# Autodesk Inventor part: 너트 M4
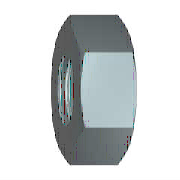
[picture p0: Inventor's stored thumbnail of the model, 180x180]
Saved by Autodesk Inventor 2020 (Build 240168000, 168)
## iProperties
IsCustomPart: 0
Created: 2012-02
Part Number: 너트 M4
Material: 스테인리스강
Description: 6각 너트, 스타일 1 - 제품 등급 A 및 B
Document SubType Name: Modeling
Standard: ISO 4032
Designer: mduedu
Standard Revision: Third edition 1999-08-15
Standards Organization: ISO
Language: ko-KR
Size Designation: M4
Categories: <MemberInstance><Categories><Category DisplayName="조임쇠" InternalName="e4da775c-781d-43d5-af7c-5136215cf5a6" Mnemonic="FSTN"><Category DisplayName="너트" InternalN
Density: 8.08 g/cm^3
Mass: 0.820715 g
Surface Area: 1.59496 cm^2
Volume: 0.101574 cm^3
Appearance: 반광택
Author: mduedu
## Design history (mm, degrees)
sketch "스케치1"
  geometry: L1 (-4.041, 0)-(-2.021, 3.5); L2 (-2.021, 3.5)-(2.021, 3.5); L3 (2.021, 3.5)-(4.041, 0); L4 (4.041, 0)-(2.021, -3.5); L5 (2.021, -3.5)-(-2.021, -3.5); L6 (-2.021, -3.5)-(-4.041, 0); 2 further points
  constraints: 12 end point, 1 coincident, 1 horizontal, 11 other
  dimensions: "d0" = 8.0829 distance of L3.end L1.start (= 1.1547 x SW)
extrude "본체" new body sketch "스케치1" distance "d1" = 3.2 (= KOH); taper "d2" = 0 deg
sketch "스케치2"
  geometry: L1 (0, 2.021)-(0, 4.041) reference; L2 (0, 4.041)-(3.2, 4.041) reference; L3 (3.2, 2.021)-(3.2, 4.041) reference; L4 (-0.64, 0)-(3.84, 0) reference; L5 (0.63, 4.041)-(0, 2.95); L6 (2.57, 4.041)-(3.2, 2.95)
  constraints: 4 end point, 4 point on line
  dimensions: "d3" = 30 deg angle of L1 L5 (= ANG1); "d4" = 30 deg angle of L3 L6 (= ANG2); "d5" = 5.9 diameter of L5.end L4 (= SW0); "d6" = 5.9 diameter of L6.end L4 (= SW01)
revolve "모따기1" sketch "스케치2" stored, may be unused: angle "d7" = 90 deg
sketch "스케치3"
  geometry: 4 further points
  constraints: 1 coincident, 1 other
hole "스레드" sketch "스케치3" at (0, 0) diameter "d25" = 3.242; stored, may be unused: countersink angle "d29" = 82 deg, drill point angle "d31" = 118 deg; dims "d26" = 6, "d27" = 4, "d28" = 2, "d30" = 8
workaxis "Work Axis1"
workplane "Work Plane1"
body "Solid1"
chamfer "모따기2" distance "d8" = 0.37889 (= -0.5 x GD1 + 0.5 x NND); stored, may be unused: angle "d9" = 30 deg, second distance "d40" = 0.37889 (= -0.5 x GD1 + 0.5 x NND)
chamfer "모따기3" distance "d10" = 0.37889 (= -0.5 x GD1 + 0.5 x NND); stored, may be unused: angle "d11" = 30 deg, second distance "d41" = 0.37889 (= -0.5 x GD1 + 0.5 x NND)
other parameters: "ANG1" = 30 deg [user parameter; used in 1 equation term], "ANG2" = 30 deg [user parameter; used in 1 equation term], "NND" = 4 [user parameter; used in 4 equation terms], "KOH" = 3.2 [user parameter; used in 1 equation term], "SW" = 7 [user parameter; used in 2 equation terms], "SW0" = 5.9 [user parameter; used in 2 equation terms], "SW01" = 5.9 (= SW0) [user parameter; used in 1 equation term], "GD1" = 3.24223 (computed from THREADDIA, PTC, TOA) [user parameter; used in 4 equation terms], "d13" = 0, "d14" = 0, "d39" = 0, "d42" = 0, "GUL" = 0.37889 (= 0.541266 x PTC) [user parameter], "TPU" = 14.28571 (computed from PTC) [user parameter], "THREADDIA" = 4 [user parameter; used in 1 equation term], "TOA" = 30 deg [user parameter; used in 1 equation term], "PTC" = 0.7 [user parameter; used in 4 equation terms], "E0" = 8.085 (= 1.155 x SW) [user parameter], "GAL" = 0.37889 (= 0.541266 x PTC) [user parameter]
